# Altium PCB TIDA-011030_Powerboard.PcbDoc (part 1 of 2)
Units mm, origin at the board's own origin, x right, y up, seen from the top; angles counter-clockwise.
Board outline 86.79 x 21.79 mm, 4 copper layers (Top Layer, Mid Layer 1, Mid Layer 2, Bottom Layer), stack 1.57 mm thick; 19 components, 12 nets, 39 pads, 602 vias.
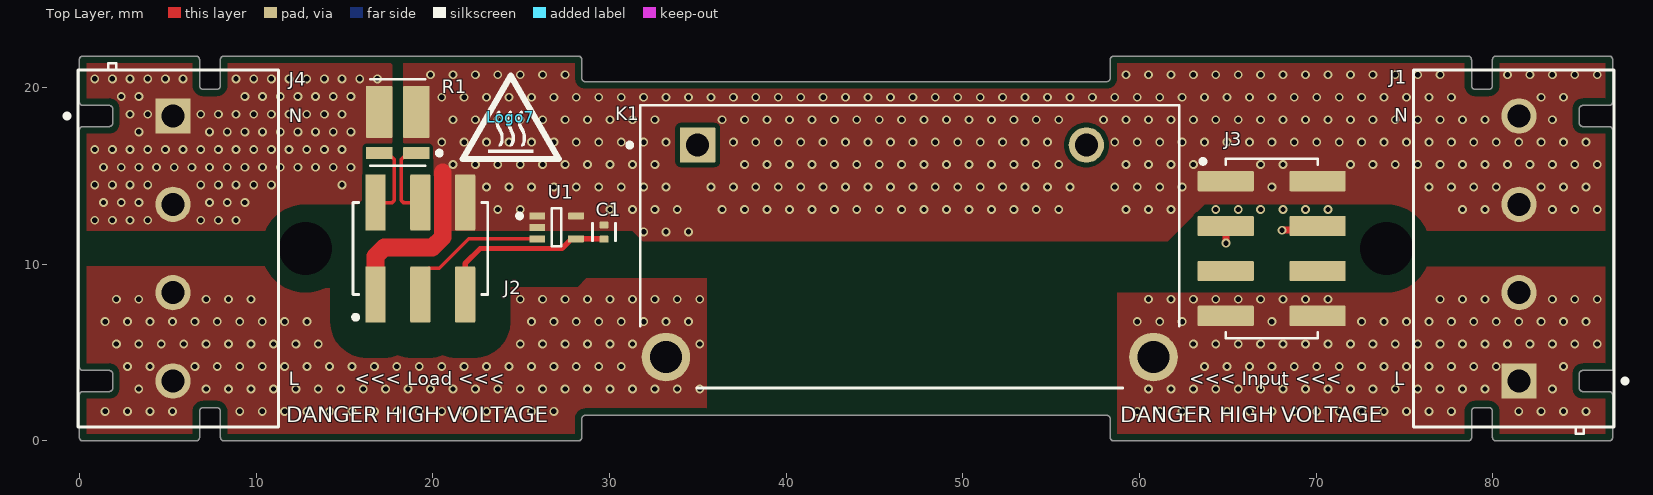
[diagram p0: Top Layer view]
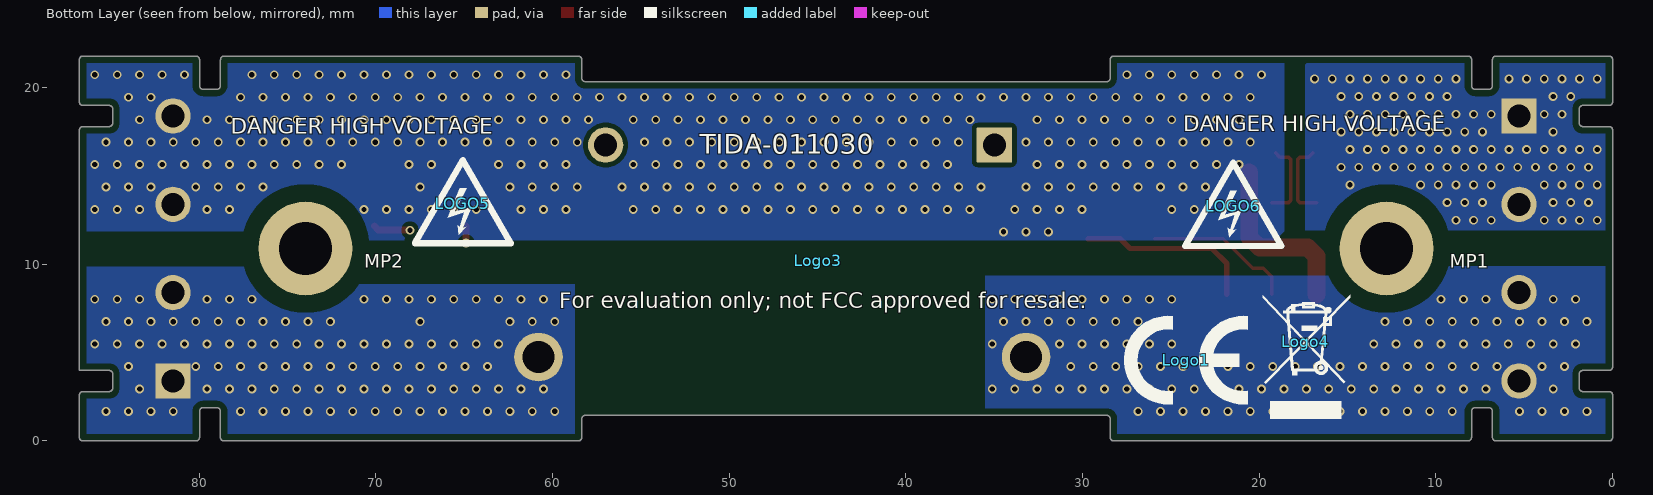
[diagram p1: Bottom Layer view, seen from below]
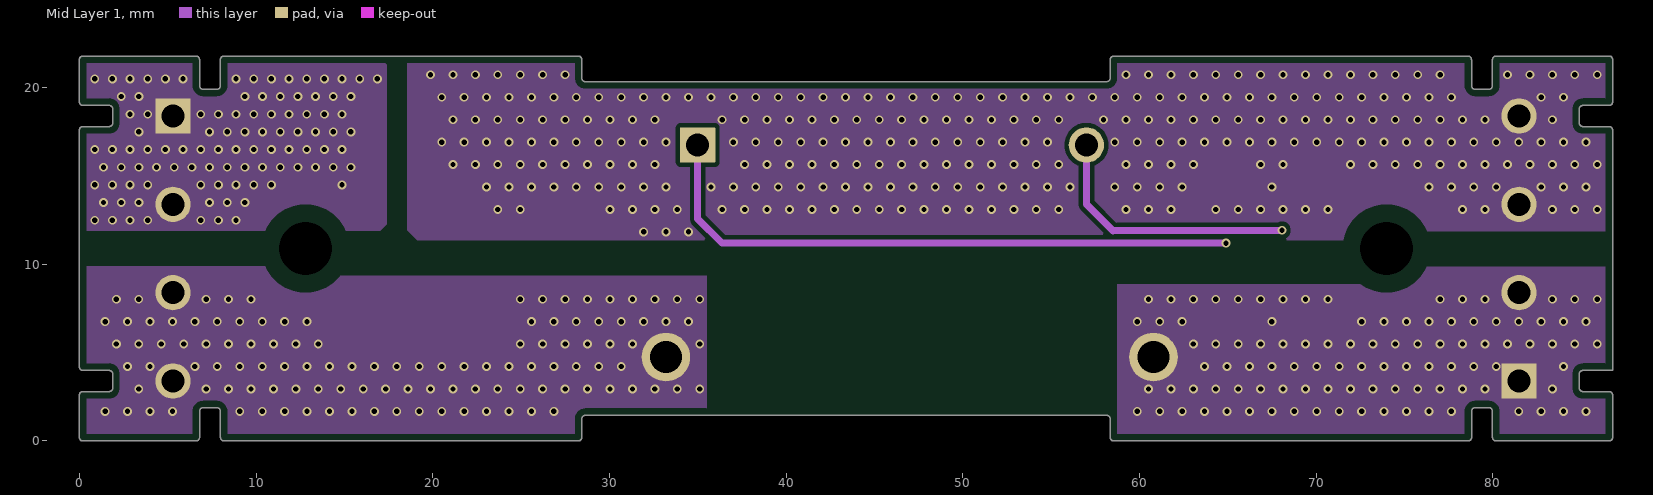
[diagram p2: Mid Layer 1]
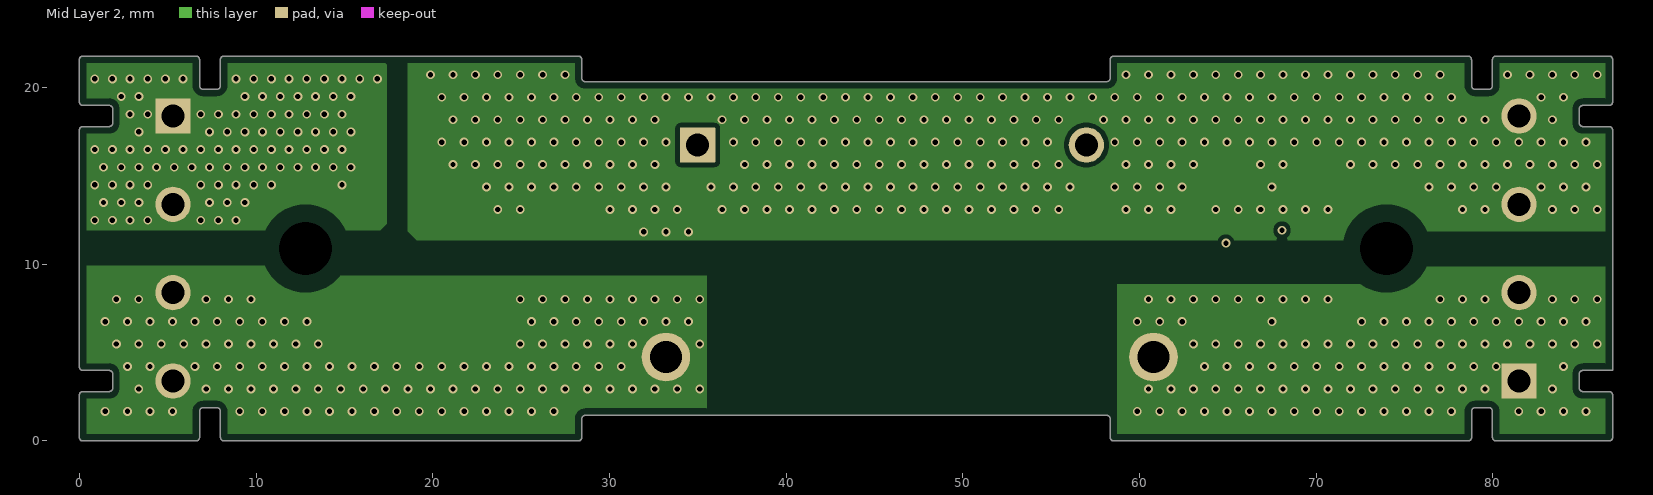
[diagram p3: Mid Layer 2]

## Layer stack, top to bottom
Top Solder: solder mask 0.0127, Solder Resist, Dk 3.8
Top Layer: signal copper 0.035
Dielectric 1: prepreg 0.1, 2313, Dk 4.05
Mid Layer 1: signal copper 0.0175
Core: core 1.265, FR-4, Dk 4.5
Mid Layer 2: signal copper 0.0175
Dielectric 2: prepreg 0.1, 2313, Dk 4.05
Bottom Layer: signal copper 0.035
Bottom Solder: solder mask 0.0127, Solder Resist, Dk 3.8

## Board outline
0.001,0.2 0,2.595 0,2.594 cw(c0.2,2.594) 0.2,2.794 1.686,2.797 ccw(c1.686,2.997) 1.886,2.997 1.886,2.995 1.886,3.795 ccw(c1.686,3.795) 1.686,3.995 0.2,3.995 0.201,3.995 cw(c0.201,4.195) 0.001,4.195 0,4.195 0,17.595 0,17.594 cw(c0.2,17.594) 0.2,17.794 0.2,17.795 1.686,17.797 ccw(c1.686,17.997) 1.886,17.997 1.886,17.995 1.886,18.795 ccw(c1.686,18.795) 1.686,18.995 0.2,18.995 0.201,18.995 cw(c0.201,19.195) 0.001,19.195 0,19.195 0,21.59 0,21.589 cw(c0.2,21.589) 0.2,21.789 0.2,21.79 6.604,21.79 cw(c6.604,21.59) 6.804,21.59 6.804,20.104 6.805,20.104 ccw(c7.005,20.104) 7.005,19.904 7.004,19.904 7.786,19.904 7.786,19.905 ccw(c7.786,20.105) 7.986,20.105 7.986,20.104 7.986,21.59 7.986,21.589 cw(c8.186,21.589) 8.186,21.789 28.239,21.79 cw(c28.239,21.59) 28.439,21.59 28.439,20.54 28.44,20.54 ccw(c28.64,20.54) 28.64,20.34 28.639,20.34 58.151,20.34 58.151,20.342 ccw(c58.151,20.542) 58.351,20.542 58.351,20.54 58.351,21.59 58.351,21.589 cw(c58.551,21.589) 58.551,21.789 78.595,21.79 78.594,21.79 cw(c78.594,21.59) 78.794,21.59 78.804,21.59 78.804,20.104 78.805,20.104 ccw(c79.005,20.104) 79.005,19.904 79.004,19.904 79.786,19.904 79.786,19.905 ccw(c79.786,20.105) 79.986,20.105 79.986,20.104 79.986,21.59 79.986,21.589 cw(c80.186,21.589) 80.186,21.789 80.186,21.79 86.59,21.79 86.589,21.79 cw(c86.589,21.59) 86.789,21.59 86.79,21.59 86.79,19.195 86.79,19.197 cw(c86.59,19.197) 86.59,18.997 86.59,18.995 85.104,18.995 85.104,18.994 ccw(c85.104,18.794) 84.904,18.794 84.904,18.795 84.904,17.995 84.905,17.995 ccw(c85.105,17.995) 85.105,17.795 85.104,17.795 86.59,17.795 86.589,17.795 cw(c86.589,17.595) 86.789,17.595 86.79,17.595 86.79,3.995 85.104,3.995 ccw(c85.104,3.795) 84.904,3.795 84.905,2.995 ccw(c85.105,2.995) 85.105,2.795 85.104,2.795 86.59,2.795 86.589,2.795 cw(c86.589,2.595) 86.789,2.595 86.79,2.595 86.79,0.2 86.79,0.201 cw(c86.59,0.201) 86.59,0.001 80.186,0 80.188,0 cw(c80.188,0.2) 79.988,0.2 79.987,1.686 ccw(c79.787,1.686) 79.787,1.886 79.004,1.886 ccw(c79.004,1.686) 78.804,1.686 78.804,0.2 cw(c78.604,0.2) 78.604,0 58.551,0 58.553,0 cw(c58.553,0.2) 58.353,0.2 58.35,1.25 ccw(c58.15,1.25) 58.15,1.45 58.151,1.45 28.639,1.45 ccw(c28.639,1.25) 28.439,1.25 28.439,0.2 cw(c28.239,0.2) 28.239,0 8.186,0 8.188,0 cw(c8.188,0.2) 7.988,0.2 7.985,1.686 ccw(c7.785,1.686) 7.785,1.886 7.786,1.886 7.004,1.885 ccw(c7.004,1.685) 6.804,1.685 6.804,1.686 6.804,0.2 6.804,0.201 cw(c6.604,0.201) 6.604,0.001 0.2,0 0.201,0 cw(c0.201,0.2)

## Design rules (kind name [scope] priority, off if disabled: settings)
AcuteAngle [All] p1: minimum=4.50000000000000E+0001 checktracksonly=FALSE
AssemblyTestPointUsage [All] p1: valid=2
BoardOutlineClearance BoardOutlineClearance_MountingHoles [OnCopper and InComponentClass('Mounting Holes')] p1: gap=1 ignorepadtopadclearanceinfootprint=FALSE
BoardOutlineClearance BoardOutlineClearance_Poly [OnCopper and IsPoly] p2: gap=0.4 ignorepadtopadclearanceinfootprint=FALSE
BoardOutlineClearance [OnCopper and Not InComponentClass('Logo') and not InComponentClass('FiducialMark') and not InRegion(1000,500,4000,800) and not InPoly] p3: gap=0.4 ignorepadtopadclearanceinfootprint=FALSE
Clearance LV-MP2 [InNetClass('LV') vs InNet('MP2')] p1: gap=1 ignorepadtopadclearanceinfootprint=FALSE
Clearance LV-MP1 [InNetClass('LV') vs InNet('MP1')] p2: gap=1 ignorepadtopadclearanceinfootprint=FALSE
Clearance HV-MP2 [InNetClass('HV') vs InNet('MP2')] p3: gap=1 ignorepadtopadclearanceinfootprint=FALSE
Clearance HV-MP1 [InNetClass('HV') vs InNet('MP1')] p4: gap=1 ignorepadtopadclearanceinfootprint=FALSE
Clearance HV-LV [InNetClass('HV') vs InNetClass('LV')] p5: gap=2 ignorepadtopadclearanceinfootprint=TRUE
Clearance HV-HV [InNetClass('HV') vs InNetClass('HV')] p6: gap=1 ignorepadtopadclearanceinfootprint=TRUE
Clearance [InNetClass('LV') vs InNetClass('LV')] p7: gap=0.2 ignorepadtopadclearanceinfootprint=TRUE
Clearance Clearance_Keepouts [((IsTrack Or IsArc) And Not InPoly) And IsFree and IsKeepOut vs ((IsTrack Or IsArc) And Not InPoly) And IsFree and IsKeepOut] p8: gap=0 ignorepadtopadclearanceinfootprint=FALSE
Clearance Clearance_Poly [InPolygon] p9: gap=0.254 ignorepadtopadclearanceinfootprint=TRUE
Clearance Clearance_FiducialMark [IsKeepOut and InComponentClass('FiducialMark') vs IsPad and InComponentClass('FiducialMark')] p10: gap=0 ignorepadtopadclearanceinfootprint=FALSE
ComponentClearance ComponentClearance_MountingHoles_FiducialMarks [InComponentClass('Mounting Holes') vs InComponentClass('FiducialMark')] p1: gap=1.27 collisioncheckmode=3 verticalgap=0.254 showdistances=FALSE
ComponentClearance ComponentClearance_Shunt [InComponentClass('Header') vs InComponentClass('Shunt')] p2: gap=0 collisioncheckmode=3 verticalgap=0 showdistances=FALSE
ComponentClearance ComponentClearance_Logo [InComponentClass('Logo')] p3: gap=0.762 collisioncheckmode=3 verticalgap=0.254 showdistances=FALSE
ComponentClearance ComponentClearance_ScrewToNut [(HasFootprint('NY PMS 440 0025 PH')) vs (HasFootprint('Keystone_1902C'))] p4: gap=0.127 collisioncheckmode=3 verticalgap=0.254 showdistances=FALSE
ComponentClearance ComponentClearance_MountingHoles [InComponentClass('Mounting Holes')] p5: gap=2.54 collisioncheckmode=3 verticalgap=2540 showdistances=FALSE
ComponentClearance ComponentClearance_SmallPassives [HasFootprint('0201*') or HasFootprint('0402*') or HasFootprint('0508') or HasFootprint('0603*') or HasFootprint('0612') or HasFootprint('0805*') or HasFootprint('0815*') or HasFootprint('0830*') or HasFootprint('1206*') or HasFootprint('1210*') or HasFootprint('1808*') or HasFootprint('1812*') or HasFootprint('1825*') or HasFootprint('2010*') or HasFootprint('2220*') or HasFootprint('2225*') or HasFootprint('2512*') or HasFootprint('2728*') or HasFootprint('3518*') vs HasFootprint('0201*') or HasFootprint('0402*') or HasFootprint('0508') or HasFootprint('0603*') or HasFootprint('0612') or HasFootprint('0805*') or HasFootprint('0815*') or HasFootprint('0830*') or HasFootprint('1206*') or HasFootprint('1210*') or HasFootprint('1808*') or HasFootprint('1812*') or HasFootprint('1825*') or HasFootprint('2010*') or HasFootprint('2220*') or HasFootprint('2225*') or HasFootprint('2512*') or HasFootprint('2728*') or HasFootprint('3518*')] p6: gap=0.38 collisioncheckmode=3 verticalgap=0.254 showdistances=FALSE
ComponentClearance ComponentClearance_THtoSMT [IsThruComponent vs IsSMTComponent] p7: gap=0.762 collisioncheckmode=3 verticalgap=0.762 showdistances=FALSE
ComponentClearance ComponentClearance_THtoTH [IsThruComponent vs IsThruComponent] p8: gap=0.508 collisioncheckmode=3 verticalgap=0.762 showdistances=FALSE
ComponentClearance [All] p9: gap=0.508 collisioncheckmode=3 verticalgap=0.254 showdistances=FALSE
DiffPairsRouting DiffPairsRouting_Shunt [All] p1: maxlimit=2.54 minlimit=0.2 mostfreqgap=0.2 toplayer_minwidth=0.15 toplayer_maxwidth=0.381 toplayer_prefwidth=0.15 midlayer1_minwidth=0.15 midlayer1_maxwidth=0.381 midlayer1_prefwidth=0.15 midlayer2_minwidth=0.15 midlayer2_maxwidth=0.381 midlayer2_prefwidth=0.15 bottomlayer_minwidth=0.15 bottomlayer_maxwidth=0.381 bottomlayer_prefwidth=0.15 maxuncoupledlength=25.4
FabricationTestPointUsage TestPointUsage [All] p1: valid=2 allowmultiple=FALSE
FabricationTestpoint Testpoint [All] p1: side=3 testpointundercomponent=TRUE minsize=1.016 maxsize=2.54 preferedsize=1.524 minholesize=0 maxholesize=1.016 preferedholesize=0.813 testpointgrid=0.025 allowsidetop=TRUE allowsidebottom=TRUE usegrid=TRUE gridtolerance=0
FanoutControl Fanout_LCC [IsLCC] p1: bgadir=Out bgaviamode=Centered fanoutstyle=Auto fanoutdirection=Alternating viagrid=0.025 // Fanout_LCC (Default Rule)
FanoutControl Fanout_BGA [IsBGA] p2: bgadir=Out bgaviamode=Centered fanoutstyle=Auto fanoutdirection=Alternating viagrid=0.025 // Fanout_BGA (Default Rule)
FanoutControl Fanout_Default [All] p4: bgadir=Out bgaviamode=Centered fanoutstyle=Auto fanoutdirection=Alternating viagrid=0.025 // Fanout_Default (Default Rule)
FanoutControl Fanout_Small [(CompPinCount < 5)] p5: bgadir=Out bgaviamode=Centered fanoutstyle=Auto fanoutdirection=OutThenIn viagrid=0.025 // Fanout_Small (Default Rule)
HoleSize [All] p1: absolutevalues=TRUE maxlimit=6.375 minlimit=0.2 maxpercent=80.000 minpercent=20.000
MinimumAnnularRing MinimumAnnularRing_ThermalPadVias [IsVia and InAnyComponent] p1: minimumring=0.15
MinimumAnnularRing [All] p2: minimumring=0.1
MinimumSolderMaskSliver MinimumSolderMaskSliver_Logo [InComponentClass('Logo') vs InComponentClass('Logo')] p1: minsoldermaskwidth=0.018
MinimumSolderMaskSliver [All] p2: minsoldermaskwidth=0.1
PlaneConnect [All] p1: planeconnectstyle=Relief reliefexpansion=0.254 reliefentries=4 reliefconductorwidth=0.254 reliefairgap=0.254
PolygonConnect [All] p1: connectstyle=Relief reliefconductorwidth=0.254 reliefentries=4 polygonreliefangle="90 Angle" airgapwidth=0.254
RoutingLayers [All] p1: top layer_v5=TRUE mid layer 1_v5=FALSE mid layer 2_v5=FALSE bottom layer_v5=TRUE
RoutingVias ThermalPadVias [IsVia and InAnyComponent] p1: holewidth=0.4 width=0.6 viastyle="Through Hole" minholewidth=0.2 minwidth=0.5 maxholewidth=0.5 maxwidth=0.8
RoutingVias [All] p2: holewidth=0.406 width=0.5 viastyle="Through Hole" minholewidth=0.3 minwidth=0.61 maxholewidth=1.016 maxwidth=1.651
SilkToBoardRegionClearance [Not ((IsComment or IsDesignator) And (Hide <> 'False')) and not InRegion(1000,500,4000,800)] p1:
SilkToSilkClearance SilkToSilkClearance_Pb-FreeLogo [(HasFootprint('Pb-Free_Overlay_Medium') OR HasFootprint('Pb-Free_Overlay_Small')) vs (HasFootprint('Pb-Free_Overlay_Medium') OR HasFootprint('Pb-Free_Overlay_Small'))] p1: silktosilkclearance=0
SilkToSilkClearance [All] p2: silktosilkclearance=0.1
SilkToSolderMaskClearance SilkToComponentPadClearance [(IsPad or IsFill or IsRegion) and InAnycomponent] p1: minsilkscreentomaskgap=0.127 clearancetoexposedcopper=TRUE
SilkToSolderMaskClearance "Silk to Solder Mask Opening" [All] p2: minsilkscreentomaskgap=0.1 clearancetoexposedcopper=FALSE
SolderMaskExpansion [All] p1: expansion=0.05 istentingtop=FALSE
SupplyNets "Schematic Supply Nets" [InNet('Neutral')] p1: voltage=0.000
SupplyNets "Schematic Supply Nets_1" [InNet('3.3V')] p2: voltage=0.000
UnRoutedNet [All] p1: checkbadconnections=TRUE
Width [All] p1: maxlimit=2.54 minlimit=0.152 preferedwidth=0.2 checkconnectedcopper=TRUE
13 further rules are at their usual default settings.

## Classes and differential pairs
net class LV: 3.3V I_N I_P MCU_Temp NetJ4_1 Neutral
net class HV: Line MP1 MP2 NetJ4_3
component class TIDA-011030_Powerboard: C1 J1 J2 J3 J4 K1 R1 U1
component class TIDA-011030_Powerboard_Hardware: Logo1 Logo3 Logo4 LOGO5 LOGO6 Logo7 MP1 MP2 ZZ1 ZZ2 ZZ3
component class AssemblyNote: ZZ1 ZZ2 ZZ3
differential pair I: +I_P -I_N

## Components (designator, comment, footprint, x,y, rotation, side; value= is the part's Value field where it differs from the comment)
C1 "GRM155R71H104KE14D" FP-GRM155R71H104KE14D_0402-MFG 29.7,11.825 r270 top value=100nF
J1 "1710878" FP-1710878_TERM_BLK_4-MFG 81.19,10.895 r90 top
J2 "HW-03-11-L-D-649-SM" FP-HW-03-11-L-D-649-SM_HDR8-MFG 19.3,10.895 r0 top
J3 "HW-04-11-L-D-649-SM" FP-HW-04-11-L-D-649-SM_HDR8-MFG 67.49,10.895 r270 top
J4 "1710878" FP-1710878_TERM_BLK_4-MFG 5.6,10.895 r270 top
K1 "G6QE-1A DC5" "FP-G6QE-1A DC5_PTH_RELAY_30MM5_16MM0-MFG" 47,11 r0 top
Logo1 "CE Mark" CE_Mark_5mm 24.15,4.575 r180 bottom
Logo3 "FCC disclaimer" FCC_disclaimer 44.975,10.2 r180 bottom
Logo4 "WEEE logo" WEEE_Minimum 17.375,5.625 r180 bottom
LOGO5 "DANGER HIGH VOLTAGE" IEC_HighVoltage_Small 65.075,13.425 r180 bottom
LOGO6 "DANGER HIGH VOLTAGE" IEC_HighVoltage_Small 21.475,13.275 r180 bottom
Logo7 "CAUTION HOT SURFACE" IEC_HotSurface_Small 24.425,18.325 r0 top
MP1 "9774040243R" 9774040243 12.8,10.895 r180 bottom
MP2 "9774040243R" 9774040243 73.99,10.895 r180 bottom
R1 "WSK12161L000FEA" FP-WSK12161L000FEA_1216-MFG 18.025,18.025 r180 top value=0.001
U1 "TMP236A2DCKR" DCK0005A-MFG 27.017,12.091 r0 top
ZZ1 "These assemblies are ESD sensitive, ESD precautions shall be observed." AssemblyNote 4.324,32.562 r0 top
ZZ2 "These assemblies must be clean and free from flux and all contaminants. Use of no clean flux is not acceptable." AssemblyNote 4.324,30.344 r0 top
ZZ3 "These assemblies must comply with workmanship standards IPC-A-610 Class 2, unless otherwise specified." AssemblyNote 4.324,28.126 r0 top

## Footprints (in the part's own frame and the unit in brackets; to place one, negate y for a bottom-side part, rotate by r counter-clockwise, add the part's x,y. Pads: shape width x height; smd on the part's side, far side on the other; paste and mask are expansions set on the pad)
9774040243 [mm] "SMT Steel Spacer with internal Thread M2, height 4mm"
  round 5.3 / inner round 0 / far side round 0 hole 3 unplated: 1(0,0)
  body extent -2.17,-2.16 2.18,2.16, height 4
AssemblyNote [mm] "Assembly Note"
CE_Mark_5mm [mm] "Minimum text height for CE Mark"
  silkscreen extent -3.5,-2.5 3.5,2.5
DCK0005A-MFG [mm] "Recommended Land Pattern"
  rrect25% 0.9x0.4 smd paste-1000 mask+0: 1(-1.1,0.65) 2(-1.1,0) 3(-1.1,-0.65) 4(1.1,-0.65) 5(1.1,0.65)
  silkscreen extent -2.22,-1.07 0.27,1.07, body extent -1.65,-1.33 1.65,1.33, height 0.25
FCC_disclaimer [mm]
FP-1710878_TERM_BLK_4-MFG [mm] "Recommended Land Pattern"
  rrect5% 2x2 hole 1.3 paste-2539.97 mask+0: 1(-7.5,-0.3)
  round 2 hole 1.3 paste-2539.97 mask+0: 2(-2.5,-0.3) 3(2.5,-0.3) 4(7.5,-0.3)
  silkscreen extent -10.49,-6.43 10.1,5.68, body extent -10.56,-5.61 10.04,5.54, height 18.2
"FP-G6QE-1A DC5_PTH_RELAY_30MM5_16MM0-MFG" [mm]
  rrect5% 2x2 hole 1.3 paste-2539.97 mask+0: 1(-12,5.75)
  round 2 hole 1.3 paste-2539.97 mask+0: 2(10,5.75)
  round 2.75 hole 1.8 paste-2539.97 mask+0: 3(13.8,-6.25) 4(-13.8,-6.25)
  silkscreen extent -15.97,-8 15.25,8, body extent -15.35,-8.1 15.35,8.1, height 0.25
FP-GRM155R71H104KE14D_0402-MFG [mm]
  rrect25% 0.4x0.5 smd paste+0 mask+0: 1(-0.4,0) 2(0.4,0)
  silkscreen extent -0.5,-0.65 0.5,0.65, body extent -0.7,-0.38 0.7,0.38, height 0.25
FP-HW-03-11-L-D-649-SM_HDR8-MFG [mm] "Recommended Land Pattern"
  rrect9% 1.14x3.175 smd paste+0 mask+0: 1(-2.54,-2.602) 2(-2.54,2.602) 3(0,-2.602) 4(0,2.602) 5(2.54,-2.602) 6(2.54,2.602)
  silkscreen extent -3.81,-4.01 3.81,2.61, body extent -3.81,-3.75 3.81,3.75, height 22.1
FP-HW-04-11-L-D-649-SM_HDR8-MFG [mm] "Recommended Land Pattern"
  rrect9% 1.14x3.175 smd paste+0 mask+0: 1(-3.81,-2.602) 2(-3.81,2.602) 3(-1.27,-2.602) 4(-1.27,2.602) 5(1.27,-2.602) 6(1.27,2.602) 7(3.81,-2.602) 8(3.81,2.602)
  silkscreen extent -5.08,-4.01 5.08,2.61, body extent -5.08,-3.75 5.08,3.75, height 22.1
FP-WSK12161L000FEA_1216-MFG [mm] "SMD, 2-Leads, Body 6.45x3.35mm"
  rrect14% 1.495x0.7 smd paste+0 mask+0: 1(-1.052,1.725) 2(1.052,1.725)
  rrect7% 1.495x2.95 smd paste+0 mask+0: 3(-1.052,-0.6) 4(1.052,-0.6)
  silkscreen extent -2.48,-2.45 1.55,2.45, body extent -1.9,-2.17 1.9,2.17, height 0.25
IEC_HighVoltage_Small [mm]
  silkscreen extent -2.72,-2.24 2.72,2.47
IEC_HotSurface_Small [mm]
  silkscreen extent -2.72,-2.36 2.72,2.35
WEEE_Minimum [mm] "WEEElie bin"
  silkscreen extent -2.42,-4.38 2.52,2.65

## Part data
C1: library part CMP-0096855-1, "Chip Multilayer Ceramic Capacitors for General Purpose, 0402, 0.10uF, X7R, 15%, 10%, 50V", Manufacturer=Murata, Operating Temperature Range="-55°C to +125°C", TempCo=15%, Temperature Characteristic=X7R, Tolerance_%=10%, ValueDisplayed=0.1uF
J1 J4: library part CMP-0128751-1, "Conn PC Terminal Block F 4 POS 5mm Solder ST Thru-Hole 24A", Current_A=24A, Digikey Part Number=1710878-ND, Manufacturer="Phoenix Contact", Mouser Part Number=651-1710878, Operating Temperature Range="-40°C to +105°C", Voltage_V=400V
J2: library part CMP-0128773-1, "High Temperature Flexible Board Stacking Header for Surface Mount, 0.100\" Pitch 6 pins 2 rows", Manufacturer=Samtec, Operating Temperature Range="-55°C to +125°C"
J3: library part CMP-0128774-1, "High Temperature Flexible Board Stacking Header for Surface Mount, 0.100\" Pitch 8 pins 2 rows", Manufacturer=Samtec, Operating Temperature Range="-55°C to +125°C"
K1: library part CMP-0049581-1, "General Purpose Relay SPST-NO (1 Form A) 5VDC Coil Through Hole 32A", Coil Current_A=280mA, Coil Power_W=1.4W, Coil Resistance=17.9Ω, Coil Voltage_VDC=5V, Contact Rating_A=36A, Digikey Part Number=Z11675-ND, Manufacturer=Omron, Mouser Part Number=653-G6QE-1ADC5, Operating Temperature Range="-40°C to +60°C"
Logo1: library part CMP-0074844-1
Logo3: library part CMP-0074847-1, "FCC_disclaimer"
Logo4: library part CMP-0074769-1
LOGO5 LOGO6: library part CMP-0074835-1, "IEC 61010-1 High Voltage Warning"
Logo7: library part CMP-0074837-2, "IEC 61010-1 Hot Surface Warning", Manufacturer="Texas Instruments"
MP1 MP2: library part CMP-03913-59774868-2, "Spacer, Steel, With Internal Thread M2, 4MM Length, 4.35MM Outer Diameter", Max Operating Temperature=150°C, Min Operating Temperature=-55°C
R1: library part CMP-0097727-1, "Res Metal Strip 1216 0.001 Ohm 1% 3W ±150ppm/C Pad SMD T/R", Digikey Part Number=541-3133-1-ND, Manufacturer="Vishay Dale", Mouser Part Number=71-WSK12161L000FEA, Operating Temperature Range="-65°C to +170°C", Power_W=3W, TempCo=50ppm/°C, Tolerance_%=1%
U1: library part CMP-0124009-1, "Low-Power, High-Accuracy Analog Output Temperature Sensors", Digikey Part Number=296-TMP236A2DCKRCT-ND, Manufacturer="Texas Instruments", Max Supply Voltage=5.5V, Min Supply Voltage=3.1V, Mouser Part Number=595-TMP236A2DCKR, Operating Supply Current=10uA, Operating Temperature Range="-10°C to +125°C"
ZZ1: library part CMP-0077236-1
ZZ2: library part CMP-0077237-1
ZZ3: library part CMP-0077238-1

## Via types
v1: diameter 0.5, hole 0.3, Top Layer to Bottom Layer, tented both sides, 602 vias

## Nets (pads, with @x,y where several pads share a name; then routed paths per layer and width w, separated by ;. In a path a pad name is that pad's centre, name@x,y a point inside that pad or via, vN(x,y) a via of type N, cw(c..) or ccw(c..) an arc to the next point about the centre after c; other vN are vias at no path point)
3.3V: C1.2 J2.5 U1.4 | length 10.2
  Top Layer w0.3: J2.5@21.84,8.295 21.84,10.04 22.691,10.891 27.317,10.891 27.867,11.441 C1.2@29.684,11.441
DRV_OUT1: J3.4 K1.2 | length 17.2
  Top Layer w0.4: v1(68.075,11.925) 68.094,11.944 69.872,11.944 J3.4@70.092,12.165
  Mid Layer 1 w0.4: K1.2@57,16.75 57,13.4 58.5,11.9 v1(68.075,11.925)
DRV_OUT2: J3.3 K1.1 | length 35.6
  Top Layer w0.25: J3.3@64.89,12.165 J3.3@64.9,12.155
  Top Layer w0.4: v1(64.9,11.2) J3.3@64.9,12.155
  Mid Layer 1 w0.4: K1.1@35,16.75 35,12.575 36.375,11.2 v1(64.9,11.2)
I_N: J2.4 R1.1 | length 4.4
  Top Layer w0.2: R1.1@19.078,16.3 18.827,16.05 18.342,16.05 18.225,15.933 18.225,14.867 18.23,14.862 18.23,13.615 18.347,13.497 J2.4@19.3,13.497
I_P: J2.2 R1.2 | length 4.4
  Top Layer w0.2: J2.2@16.76,13.497 17.713,13.497 17.83,13.615 17.83,14.696 17.825,14.701 17.825,15.933 17.708,16.05 17.223,16.05 R1.2@16.973,16.3
Line: J1.1 J1.2 J3.7 J3.8 K1.3
  other v1: 59.88,1.676 61.151,1.676 62.42,1.676 63.691,1.676 64.96,1.676 66.23,1.676 67.501,1.676 68.77,1.676 70.04,1.676 71.31,1.676 72.581,1.676 73.85,1.676 75.12,1.676 76.391,1.676 77.66,1.676 81.471,1.676 82.74,1.676 84.01,1.676 85.281,1.676 60.515,2.946 61.785,2.946 63.055,2.946 64.325,2.946 65.596,2.946 66.865,2.946 68.135,2.946 69.406,2.946 70.675,2.946 71.945,2.946 73.215,2.946 74.486,2.946 75.755,2.946 77.025,2.946 78.295,2.946 79.566,2.946 83.376,2.946 63.691,4.216 64.96,4.216 66.23,4.216 67.501,4.216 68.77,4.216 70.04,4.216 71.31,4.216 72.581,4.216 73.85,4.216 75.12,4.216 76.391,4.216 77.66,4.216 78.93,4.216 80.2,4.216 84.01,4.216 63.055,5.486 64.325,5.486 65.596,5.486 66.865,5.486 68.135,5.486 69.406,5.486 70.675,5.486 71.945,5.486 73.215,5.486 74.486,5.486 75.755,5.486 77.025,5.486 78.295,5.486 79.566,5.486 80.835,5.486 82.105,5.486 83.376,5.486 84.645,5.486 85.915,5.486 59.88,6.756 61.151,6.756 62.42,6.756 67.501,6.756 72.581,6.756 73.85,6.756 75.12,6.756 76.391,6.756 77.66,6.756 78.93,6.756 80.2,6.756 81.471,6.756 82.74,6.756 84.01,6.756 85.281,6.756 60.515,8.026 61.785,8.026 63.055,8.026 64.325,8.026 65.596,8.026 66.865,8.026 68.135,8.026 69.406,8.026 70.675,8.026 77.025,8.026 78.295,8.026 79.566,8.026 83.376,8.026 84.645,8.026 85.915,8.026
MCU_Temp: J2.3 U1.3 | length 8.5
  Top Layer w0.2: J2.3@19.3,8.293 19.3,9.305 19.77,9.775 20.38,9.775 22.046,11.441 U1.3@25.917,11.441
MP1: MP1.1
MP2: MP2.1
NetJ4_1: J4.1 J4.2 R1.4
  other v1: 0.871,12.496 1.871,12.496 2.871,12.496 3.871,12.496 6.871,12.496 7.871,12.496 8.871,12.496 1.371,13.496 2.371,13.496 3.371,13.496 7.371,13.496 8.371,13.496 9.371,13.496 0.871,14.496 1.871,14.496 2.871,14.496 3.871,14.496 6.871,14.496 7.871,14.496 8.871,14.496 9.871,14.496 10.871,14.496 14.871,14.496 1.371,15.496 2.371,15.496 3.371,15.496 4.371,15.496 5.371,15.496 6.371,15.496 7.371,15.496 8.371,15.496 9.371,15.496 10.371,15.496 11.371,15.496 12.371,15.496 13.371,15.496 14.371,15.496 15.371,15.496 0.871,16.496 1.871,16.496 2.871,16.496 3.871,16.496 4.871,16.496 5.871,16.496 6.871,16.496 7.871,16.496 8.871,16.496 9.871,16.496 10.871,16.496 11.871,16.496 12.871,16.496 13.871,16.496 14.871,16.496 3.371,17.496 7.371,17.496 8.371,17.496 9.371,17.496 10.371,17.496 11.371,17.496 12.371,17.496 13.371,17.496 14.371,17.496 15.371,17.496 2.871,18.496 3.871,18.496 6.871,18.496 7.871,18.496 8.871,18.496 9.871,18.496 10.871,18.496 11.871,18.496 12.871,18.496 13.871,18.496 14.871,18.496 2.371,19.496 3.371,19.496 9.371,19.496 10.371,19.496 11.371,19.496 12.371,19.496 13.371,19.496 14.371,19.496 15.371,19.496 0.871,20.496 1.871,20.496 2.871,20.496 3.871,20.496 4.871,20.496 5.871,20.496 8.871,20.496 9.871,20.496 10.871,20.496 11.871,20.496 12.871,20.496 13.871,20.496 14.871,20.496 15.871,20.496 16.871,20.496
NetJ4_3: J4.3 J4.4 K1.4
  other v1: 1.46,1.676 2.73,1.676 4,1.676 5.271,1.676 9.08,1.676 10.351,1.676 11.62,1.676 12.89,1.676 14.16,1.676 15.43,1.676 16.7,1.676 17.97,1.676 19.241,1.676 20.511,1.676 21.78,1.676 23.05,1.676 24.32,1.676 25.59,1.676 26.86,1.676 3.365,2.946 7.175,2.946 8.445,2.946 9.716,2.946 10.986,2.946 12.255,2.946 13.525,2.946 14.795,2.946 16.066,2.946 17.335,2.946 18.605,2.946 19.875,2.946 21.145,2.946 22.415,2.946 23.685,2.946 24.956,2.946 26.226,2.946 27.495,2.946 28.765,2.946 30.035,2.946 31.305,2.946 32.575,2.946 33.846,2.946 35.115,2.946 2.73,4.216 4,4.216 6.54,4.216 7.81,4.216 9.08,4.216 10.351,4.216 11.62,4.216 12.89,4.216 14.16,4.216 15.43,4.216 16.7,4.216 17.97,4.216 19.241,4.216 20.511,4.216 21.78,4.216 23.05,4.216 24.32,4.216 25.59,4.216 26.86,4.216 28.13,4.216 29.4,4.216 30.67,4.216 2.095,5.486 3.365,5.486 4.635,5.486 5.905,5.486 7.175,5.486 8.445,5.486 9.716,5.486 10.986,5.486 12.255,5.486 13.525,5.486 24.956,5.486 26.226,5.486 27.495,5.486 28.765,5.486 30.035,5.486 31.305,5.486 35.115,5.486 1.46,6.756 2.73,6.756 4,6.756 5.271,6.756 6.54,6.756 7.81,6.756 9.08,6.756 10.351,6.756 11.62,6.756 12.89,6.756 25.59,6.756 26.86,6.756 28.13,6.756 29.4,6.756 30.67,6.756 31.941,6.756 33.21,6.756 34.48,6.756 2.095,8.026 3.365,8.026 7.175,8.026 8.445,8.026 9.716,8.026 24.956,8.026 26.226,8.026 27.495,8.026 28.765,8.026 30.035,8.026 31.305,8.026 32.575,8.026 33.846,8.026 35.115,8.026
